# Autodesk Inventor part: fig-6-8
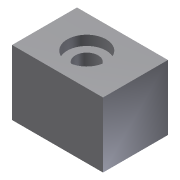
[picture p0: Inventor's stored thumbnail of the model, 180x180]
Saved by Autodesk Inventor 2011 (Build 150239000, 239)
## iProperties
Created: 2009-09
Part Number: fig-6-8
Document SubType Name: Modeling
Designer: Sham
Density: 1 g/cm^3
Author: Sham
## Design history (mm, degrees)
sketch "Sketch1"
  geometry: L1 (-28, 20)-(0, 20); L2 (0, 20)-(0, 0); L3 (0, 0)-(-28, 0); L4 (-28, 0)-(-28, 20)
  constraints: 8 end point, 2 parallel, 1 horizontal, 1 perpendicular
extrude "Extrusion1" new body sketch "Sketch1" distance "d0" = 20; taper "d1" = 0 deg
hole "Hole1" diameter "d4" = 7; stored, may be unused: countersink angle "d8" = 90 deg, drill point angle "d10" = 118 deg; dims "d2" = 10, "d3" = 15, "d5" = 6, "d6" = 12, "d7" = 3, "d9" = 15
body "Solid1"
